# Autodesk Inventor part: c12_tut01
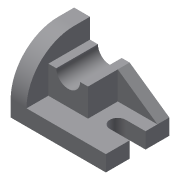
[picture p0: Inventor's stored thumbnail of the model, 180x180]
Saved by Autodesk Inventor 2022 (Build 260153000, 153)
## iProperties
Created: 2001-11
Part Number: c12_tut01
Document SubType Name: Modeling
Designer: Renu Muthoo
Density: 1 g/cm^3
Material: Generic
Appearance: Default
Control State: 0
Master: False
Checked Out: False
Shininess: 77.0
Length Units: 11269
Angle Units: 11279
Time Units: 11290
Mass Units: 11283
Length Display Precision: 3
Angle Display Precision: 2
Density: 0.0
Volumn: 0.0
Area: 0.0
PropertySet Name: Model Information
Author: Renu Muthoo
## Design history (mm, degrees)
sketch "Sketch1"
  geometry: L1 (-48, 36)-(48, 36); L2 (48, -28)-(-48, -28); L3 (-48, -28)-(-48, 36); L4 (48, 12)-(28, 12); L5 (28, -4)-(48, -4); L6 (48, 36)-(48, 12); L7 (48, -4)-(48, -28); A1 r 8 centre (28, 4) between (28, 12) and (28, -4)
  constraints: 14 end point, 4 parallel, 3 perpendicular, 2 point on circle, 2 tangent, 1 centre point, 1 collinear, 1 horizontal
  dimensions: "d0" = 96 distance of L2.start L2.end; "d1" = 64 distance of L2.end L1.start; "d2" = 20 distance of L4.start L4.end; "d3" = 24 distance between parallel lines of L2 L5; "d4" = 16 distance between parallel lines of L4 L5
extrude "Extrusion1" new body sketch "Sketch1" distance "d5" = 16; taper "d6" = 0 deg
sketch "Sketch2"
  geometry: L1 (16, 64)-(64, 64); L2 (64, 64)-(64, 48); L3 (16, 0)-(16, 0); L4 (16, 0)-(16, 64); L5 (0, 64)-(16, 64) reference; L6 (16, 0)-(16, 64) reference; L7 (0, 0)-(16, 0) reference; L8 (0, 0)-(0, 64) reference; A1 r 48 centre (16, 48) between (16, 0) and (64, 48)
  constraints: 8 end point, 3 collinear, 3 perpendicular, 2 point on circle, 2 tangent, 1 centre point, 1 horizontal
  dimensions: "d7" = 64 distance between parallel lines of L2 L8; "d8" = 48 radius of A1
extrude "Extrusion2" join sketch "Sketch2" distance "d9" = 16; taper "d10" = 0 deg
sketch "Sketch3"
  geometry: L1 (16, -44)-(16, -16); L2 (16, -16)-(56, -16); L3 (56, -16)-(56, -44); L4 (56, -44)-(48, -44); L5 (24, -44)-(16, -44); L6 (16, -64)-(16, -16) reference; L7 (16, -16)-(96, -16) reference; A1 r 12 centre (36, -44) between (48, -44) and (24, -44)
  constraints: 10 end point, 3 collinear, 3 parallel, 2 equal length, 2 point on circle, 1 centre point, 1 perpendicular, 1 point on line, 1 vertical
  dimensions: "d11" = 28 distance of L2.end L3.end; "d12" = 8 distance of L3.end L4.end; "d13" = 24 distance of L5.start L4.end
extrude "Extrusion3" join sketch "Sketch3" distance "d14" = 42; taper "d15" = 0 deg
sketch "Sketch4"
  geometry: L1 (56, -16)-(96, -16) reference; L2 (56, -16)-(56, -44) reference; L3 (96, -16)-(56, -44)
  constraints: 2 end point
extrude "Extrusion4" join sketch "Sketch4" distance "d16" = 12; taper "d17" = 0 deg
body "Solid1"
